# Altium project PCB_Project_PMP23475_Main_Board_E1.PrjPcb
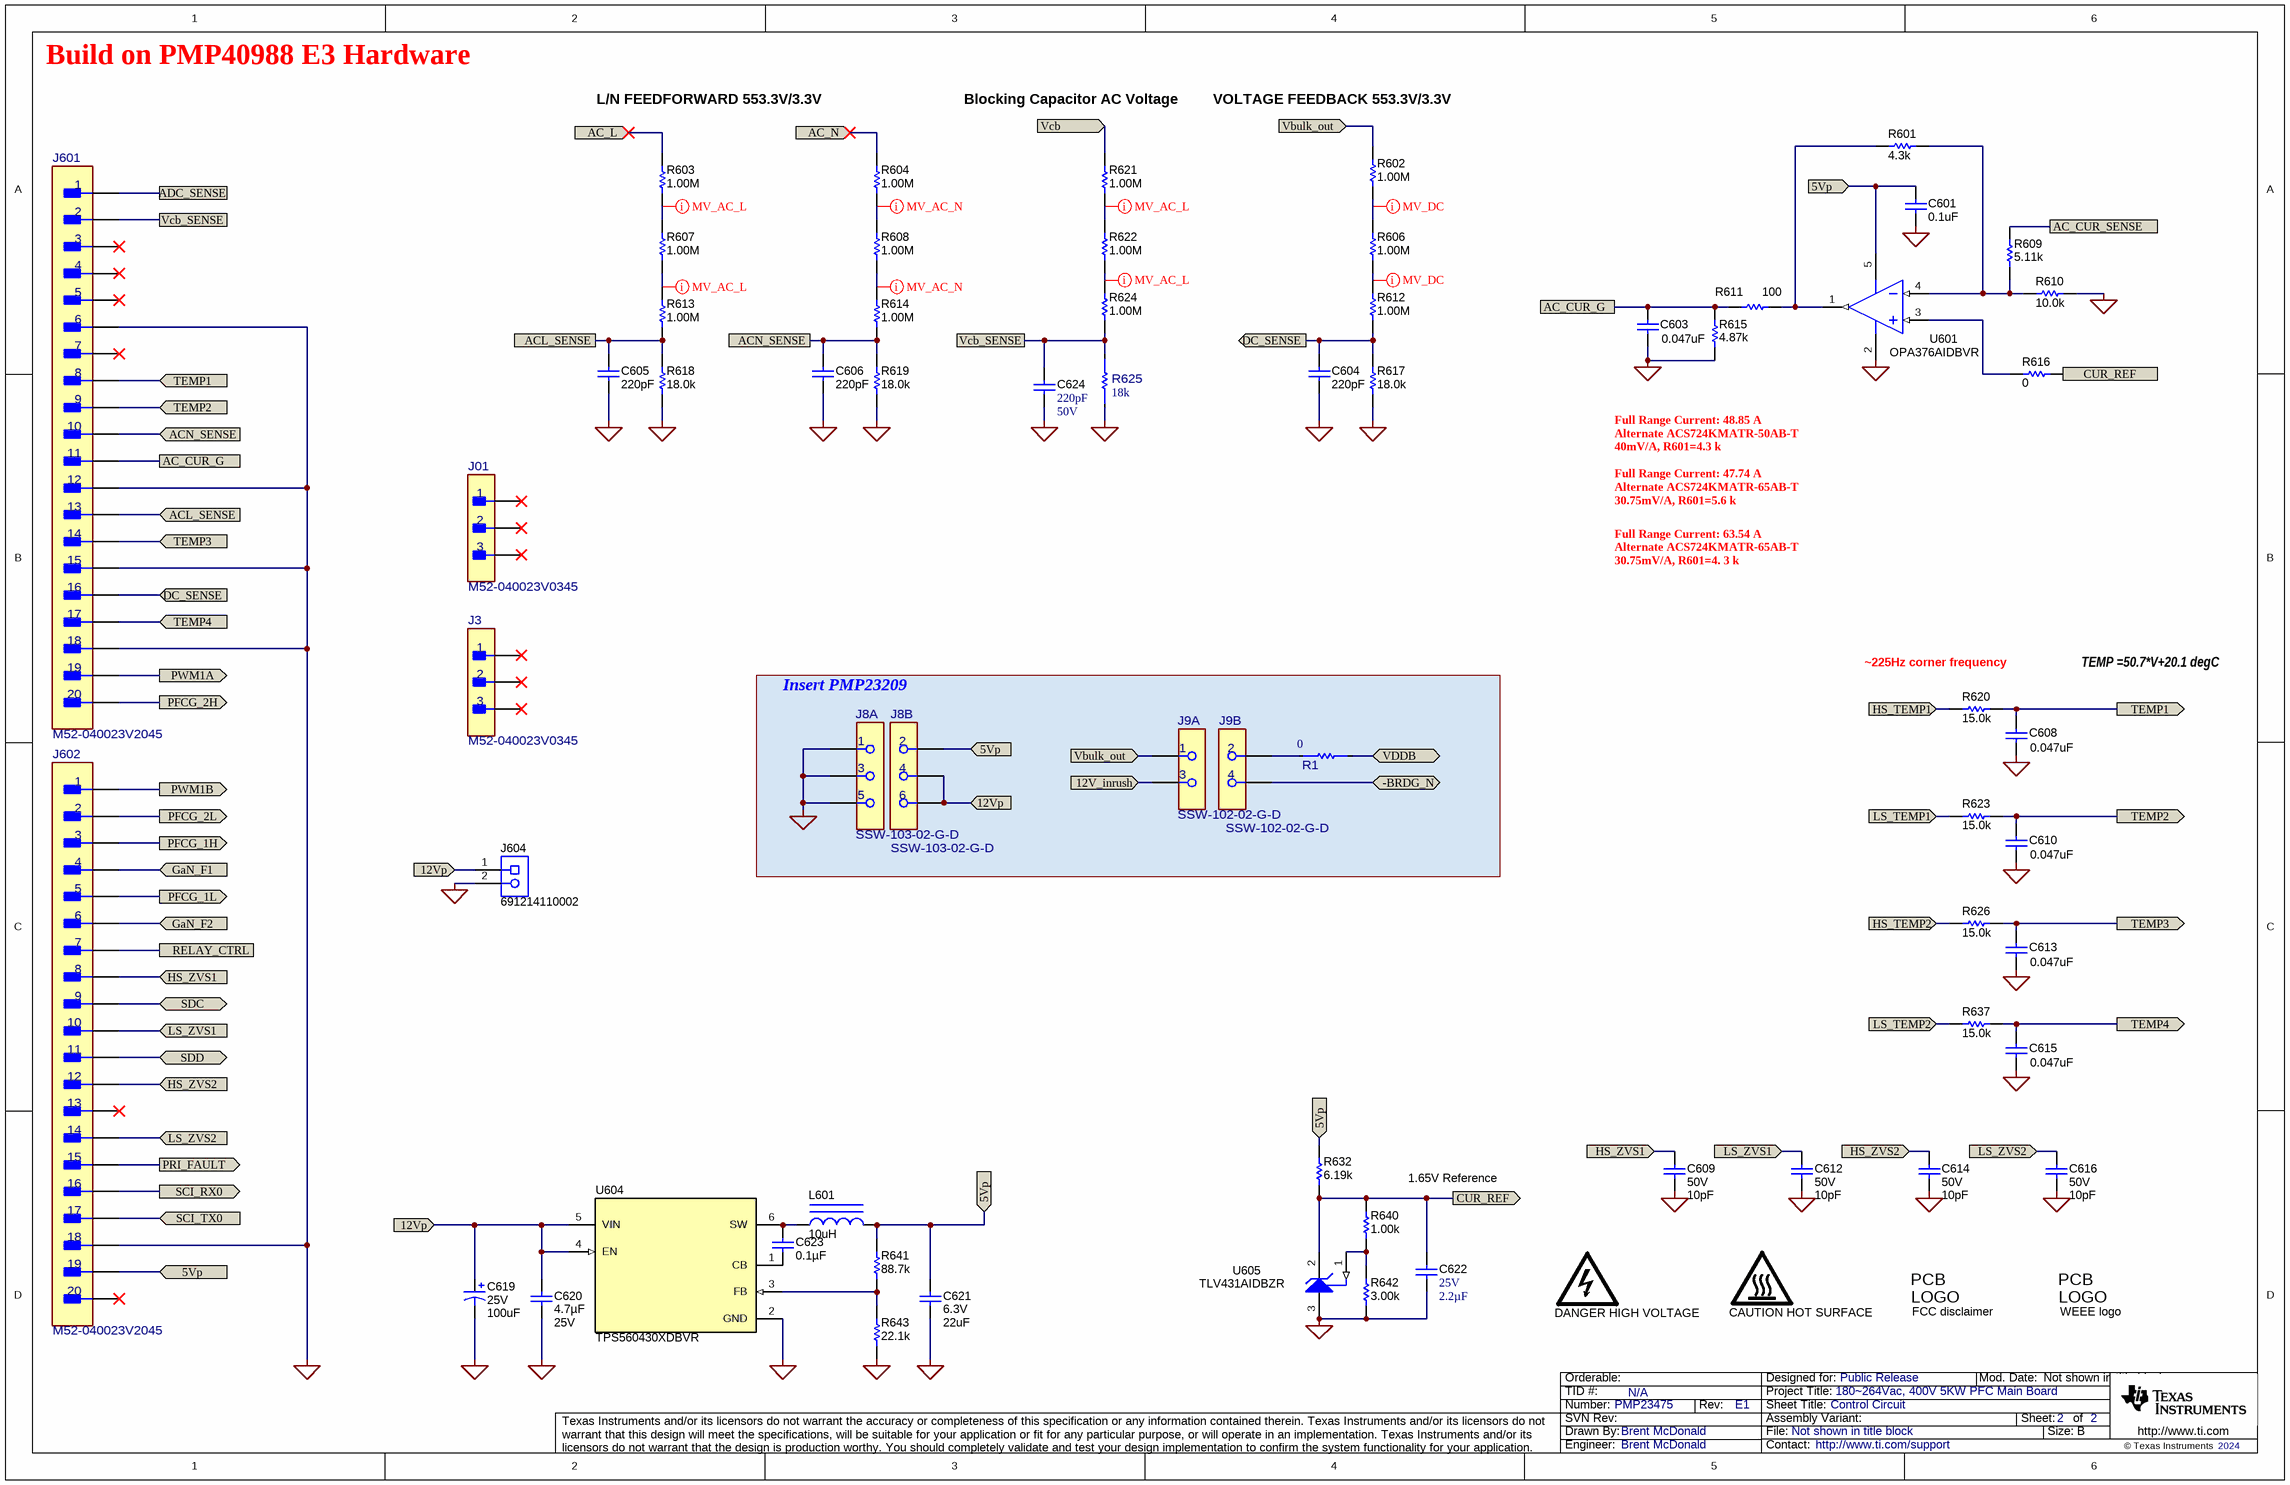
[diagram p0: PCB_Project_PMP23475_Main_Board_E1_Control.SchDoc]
CopyrightYear: 2024; PCB_Layout: Brent McDonald; PCB_Rev: E1; PRJ_Customer: Public Release; PRJ_Engineer: Brent McDonald; PRJ_Number: PMP23475; PRJ_Title: 180~264Vac, 400V 5KW PFC Main Board; SCH_Rev: E1; TechSupport: http://www.ti.com/support; TID: N/A
2 sheets, 163 parts. Net scope: flat (ports and power ports of the same name join across sheets).
Board file: PCB_Project_PPMP23475_Main_Board_E1_PCB.PcbDoc
Sheets:
  PCB_Project_PMP23475_Main_Board_E1_Control.SchDoc
  PCB_Project_PMP23475_Main_Board_E1_Power.SchDoc

## Sheet PCB_Project_PMP23475_Main_Board_E1_Control.SchDoc: Control Circuit
size 431 x 279 mm; Date: Not shown in title block; ApprovedBy: Not shown in title block; CheckedBy: Not shown in title block; Author: Not shown in title block; CompanyName: Not shown in title block; DrawnBy: Brent McDonald; Engineer: Not shown in title block; Organization: Not shown in title block; Address1: Not shown in title block; Address2: Not shown in title block; Address3: Not shown in title block; Address4: Not shown in title block; DocumentNumber: 2; Revision: Use project parameter SCH_Rev; SheetNumber: 2; SheetTotal: 2; PageSetup: Record=PageOptions¦CenterHorizontal=True¦CenterVertical=True¦PrintScale=1.00¦XCorrection=1.00¦YCorrection=1.00¦PrintKind=0¦BorderSize=5000000¦LeftOffset=0¦BottomOffset=0¦Orientation=2¦PaperLength=1000¦PaperWidth=1000¦Scale=100¦PaperSource=15¦PrintQuality=600¦MediaType=1¦DitherType=10¦PaperKind=Letter¦PrintScaleMode=1

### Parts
C601  ValueDisplayed: 0.1uF  [0402]  (hidden comment: GRM155R70J104KA01D)
C603  ValueDisplayed: 0.047uF  [0402]  (hidden comment: C1005X5R1A473K050BA)
C604  ValueDisplayed: 220pF  [0402]  (hidden comment: CC0402KRX7R9BB221)
C605  ValueDisplayed: 220pF  [0402]  (hidden comment: CC0402KRX7R9BB221)
C606  ValueDisplayed: 220pF  [0402]  (hidden comment: CC0402KRX7R9BB221)
C608  ValueDisplayed: 0.047uF  [0402]  (hidden comment: C1005X5R1A473K050BA)
C609  VDC_V: 50V  ValueDisplayed: 10pF  [0402]  (hidden comment: 885012005055)
C610  ValueDisplayed: 0.047uF  [0402]  (hidden comment: C1005X5R1A473K050BA)
C612  VDC_V: 50V  ValueDisplayed: 10pF  [0402]  (hidden comment: 885012005055)
C613  ValueDisplayed: 0.047uF  [0402]  (hidden comment: C1005X5R1A473K050BA)
C614  VDC_V: 50V  ValueDisplayed: 10pF  [0402]  (hidden comment: 885012005055)
C615  ValueDisplayed: 0.047uF  [0402]  (hidden comment: C1005X5R1A473K050BA)
C616  VDC_V: 50V  ValueDisplayed: 10pF  [0402]  (hidden comment: 885012005055)
C619  VDC_V: 25V  ValueDisplayed: 100uF  [CAPPR250W50D630H1120]  (hidden comment: EEU-EB1E101S)
C620  Cap_F: 4.7µF  VDC_V: 25V  [0805_HV]  (hidden comment: C2012X7R1E475K125AB)
C621  VDC_V: 6.3V  ValueDisplayed: 22uF  [0805_HV]  (hidden comment: CL21A226KQQNNNE)
C622  VDC_V: 25V  ValueDisplayed: 2.2µF  [0402]  (hidden comment: GRM155R61E225ME15D)
C623  ValueDisplayed: 0.1µF  [0402]  (hidden comment: CC0402KRX7R8BB104)
C624  ValueDisplayed: 220pF  VDC_V: 50V  [0402]  (hidden comment: CC0402KRX7R9BB221)
J01  M52-040023V0345  [FP-M52-040023V0345_HDR3-MFG]
J3  M52-040023V0345  [FP-M52-040023V0345_HDR3-MFG]
J8  SSW-103-02-G-D  [FP-SSW-103-02-G-D_RCPT6-MFG]  (parts A,B of 2)
J9  SSW-102-02-G-D  [FP-SSW-102-02-G-D_HDR4-MFG]  (parts A,B of 2)
J601  M52-040023V2045  [FP-M52-040023V2045_HDR20-MFG]
J602  M52-040023V2045  [FP-M52-040023V2045_HDR20-MFG]
J604  691214110002  [Wurth_691214110002]
L601  ValueDisplayed: 10uH  [WE-MAPI_3020]  (hidden comment: 74438336100)
LOGO601  CAUTION HOT SURFACE  [IEC_HotSurface_Small]  (no BOM)
LOGO602  DANGER HIGH VOLTAGE  [IEC_HighVoltage_Small]  (no BOM)
Logo603  FCC disclaimer  [FCC_disclaimer]  (no BOM)
Logo604  WEEE logo  [WEEE_Minimum]  (no BOM)
R1  value 0  [FP-ERJ-H3G0R00V_0603-MFG]  (hidden comment: ERJ-H3G0R00V)
R601  ValueDisplayed: 4.3k  [0402]  (hidden comment: RT0402FRE074K3L)
R602  ValueDisplayed: 1.00M  [1206]  (hidden comment: RC1206FR-071ML)
R603  ValueDisplayed: 1.00M  [1206]  (hidden comment: RC1206FR-071ML)
R604  ValueDisplayed: 1.00M  [1206]  (hidden comment: RC1206FR-071ML)
R606  ValueDisplayed: 1.00M  [1206]  (hidden comment: RC1206FR-071ML)
R607  ValueDisplayed: 1.00M  [1206]  (hidden comment: RC1206FR-071ML)
R608  ValueDisplayed: 1.00M  [1206]  (hidden comment: RC1206FR-071ML)
R609  ValueDisplayed: 5.11k  [0402]  (hidden comment: CRCW04025K11FKED)
R610  ValueDisplayed: 10.0k  [0402]  (hidden comment: CRCW040210K0FKED)
R611  ValueDisplayed: 100  [0402]  (hidden comment: RC0402FR-07100RL)
R612  ValueDisplayed: 1.00M  [1206]  (hidden comment: RC1206FR-071ML)
R613  ValueDisplayed: 1.00M  [1206]  (hidden comment: RC1206FR-071ML)
R614  ValueDisplayed: 1.00M  [1206]  (hidden comment: RC1206FR-071ML)
R615  ValueDisplayed: 4.87k  [0402]  (hidden comment: ERA-2AEB4871X)
R616  ValueDisplayed: 0  [0402]  (hidden comment: CRCW04020000Z0ED)
R617  ValueDisplayed: 18.0k  [0402]  (hidden comment: CRCW040218K0FKED)
R618  ValueDisplayed: 18.0k  [0402]  (hidden comment: CRCW040218K0FKED)
R619  ValueDisplayed: 18.0k  [0402]  (hidden comment: CRCW040218K0FKED)
R620  ValueDisplayed: 15.0k  [0402]  (hidden comment: RC0402FR-0715KL)
R621  ValueDisplayed: 1.00M  [1206]  (hidden comment: RC1206FR-071ML)
R622  ValueDisplayed: 1.00M  [1206]  (hidden comment: RC1206FR-071ML)
R623  ValueDisplayed: 15.0k  [0402]  (hidden comment: RC0402FR-0715KL)
R624  ValueDisplayed: 1.00M  [1206]  (hidden comment: RC1206FR-071ML)
R625  value 18k  [FP-CRCW040218K0FKEDC_0402-MFG]  (hidden comment: CRCW040218K0FKEDC)
R626  ValueDisplayed: 15.0k  [0402]  (hidden comment: RC0402FR-0715KL)
R632  ValueDisplayed: 6.19k  [0402]  (hidden comment: CRCW04026K19FKED)
R637  ValueDisplayed: 15.0k  [0402]  (hidden comment: RC0402FR-0715KL)
R640  ValueDisplayed: 1.00k  [0402]  (hidden comment: RC0402FR-071KL)
R641  ValueDisplayed: 88.7k  [0402]  (hidden comment: CRCW040288K7FKED)
R642  ValueDisplayed: 3.00k  [0402]  (hidden comment: RC0402FR-073KL)
R643  ValueDisplayed: 22.1k  [0402]  (hidden comment: CRCW040222K1FKED)
U601  OPA376AIDBVR  [DBV0005A_N]
U604  TPS560430XDBVR  [DBV0006A_N]
U605  TLV431AIDBZR  [DBZ0003A_N]

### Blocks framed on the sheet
Insert PMP23209: J8 J9 R1

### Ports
5Vp (in), 12V_inrush (in), 12Vp (in), -BRDG_N (bidir), AC_CUR_G, AC_CUR_SENSE, AC_L (in), AC_N (in), ACL_SENSE, ACL_SENSE (in), ACN_SENSE, ACN_SENSE (in), ADC_SENSE, CUR_REF (in), CUR_REF (out), DC_SENSE (in), DC_SENSE (out), GaN_F1 (in), GaN_F2 (in), HS_TEMP1 (in), HS_TEMP2 (in), HS_ZVS1 (in), HS_ZVS2 (in), LS_TEMP1 (in), LS_TEMP2 (in), LS_ZVS1 (in), LS_ZVS2 (in), PFCG_1H (out), PFCG_1L (out), PFCG_2H (out), PFCG_2L (out), PRI_FAULT (out), PWM1A (out), PWM1B (out), RELAY_CTRL, SCI_RX0 (out), SCI_TX0 (in), SDC (bidir), SDD (bidir), TEMP1 (in), TEMP1 (out), TEMP2 (in), TEMP2 (out), TEMP3 (in), TEMP3 (out), TEMP4 (in), TEMP4 (out), Vbulk_out (in), Vcb (in), Vcb_SENSE, VDDB (bidir)

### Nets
AGND: C601.1 C603.2 C604.2 C605.2 C606.2 C608.2 C609.2 C610.2 C612.2 C613.2 C614.2 C615.2 C616.2 C619.2(-) C620.2 C621.2 C622.2 C624.1 J8.1 J8.3 J8.5 J601.6 J601.12 J601.15 J601.18 J602.18 J604.2 R610.2 R615.1 R617.1 R618.1 R619.1 R625.1 R642.1 R643.1 U601.2(V-) U604.2(GND) U605.3(ANODE)
5Vp: C601.2 C621.1 J8.2 J602.19 L601.2 R632.2 R641.2 U601.5(V+) ; port 5Vp
12V_inrush: J9.3 ; port 12V_inrush
12Vp: C619.1(+) C620.1 J8.4 J8.6 J604.1 U604.4(EN) U604.5(VIN) ; port 12Vp
-BRDG_N: J9.4 ; port -BRDG_N
AC_CUR_G: C603.1 J601.11 R611.1 R615.2 ; port AC_CUR_G
AC_CUR_SENSE: R609.1 ; port AC_CUR_SENSE
AC_L: R603.2 ; port AC_L
AC_N: R604.2 ; port AC_N
ACL_SENSE: C605.1 J601.13 R613.1 R618.2 ; port ACL_SENSE
ACN_SENSE: C606.1 J601.10 R614.1 R619.2 ; port ACN_SENSE
ADC_SENSE: J601.1 ; port ADC_SENSE
CUR_REF: C622.1 R616.2 R632.1 R640.2 U605.2(CATHODE) ; port CUR_REF
DC_SENSE: C604.1 J601.16 R612.1 R617.2 ; port DC_SENSE
GaN_F1: J602.4 ; port GaN_F1
GaN_F2: J602.6 ; port GaN_F2
HS_TEMP1: R620.1 ; port HS_TEMP1
HS_TEMP2: R626.1 ; port HS_TEMP2
HS_ZVS1: C609.1 J602.8 ; port HS_ZVS1
HS_ZVS2: C614.1 J602.12 ; port HS_ZVS2
LS_TEMP1: R623.1 ; port LS_TEMP1
LS_TEMP2: R637.1 ; port LS_TEMP2
LS_ZVS1: C612.1 J602.10 ; port LS_ZVS1
LS_ZVS2: C616.1 J602.14 ; port LS_ZVS2
PFCG_1H: J602.3 ; port PFCG_1H
PFCG_1L: J602.5 ; port PFCG_1L
PFCG_2H: J601.20 ; port PFCG_2H
PFCG_2L: J602.2 ; port PFCG_2L
PRI_FAULT: J602.15 ; port PRI_FAULT
PWM1A: J601.19 ; port PWM1A
PWM1B: J602.1 ; port PWM1B
RELAY_CTRL: J602.7 ; port RELAY_CTRL
SCI_RX0: J602.16 ; port SCI_RX0
SCI_TX0: J602.17 ; port SCI_TX0
SDC: J602.9 ; port SDC
SDD: J602.11 ; port SDD
TEMP1: C608.1 J601.8 R620.2 ; port TEMP1
TEMP2: C610.1 J601.9 R623.2 ; port TEMP2
TEMP3: C613.1 J601.14 R626.2 ; port TEMP3
TEMP4: C615.1 J601.17 R637.2 ; port TEMP4
Vbulk_out: J9.1 R602.2 ; port Vbulk_out
Vcb: R621.2 ; port Vcb
Vcb_SENSE: C624.2 J601.2 R624.1 R625.2 ; port Vcb_SENSE
VDDB: R1.2 ; port VDDB
NetC623_1: C623.1 L601.1 U604.6(SW)
NetC623_2: C623.2 U604.1(CB)
NetJ9_2: J9.2 R1.1
NetR601_1: R601.1 R611.2 U601.1(OUT)
NetR601_2: R601.2 R609.2 R610.1 U601.4(IN-)
NetR602_1: R602.1 R606.2
NetR603_1: R603.1 R607.2
NetR604_1: R604.1 R608.2
NetR606_1: R606.1 R612.2
NetR607_1: R607.1 R613.2
NetR608_1: R608.1 R614.2
NetR616_1: R616.1 U601.3(IN+)
NetR621_1: R621.1 R622.2
NetR622_1: R622.1 R624.2
NetR640_1: R640.1 R642.2 U605.1(REF)
NetR641_1: R641.1 R643.2 U604.3(FB)

Not connected (* = marked no-connect by the designer): J01 1* 2* 3*; J3 1* 2* 3*; J601 3* 4* 5* 7*; J602 13* 20*

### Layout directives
net class MV_DC: NetR602_1, NetR606_1
net class MV_AC_L: NetR603_1, NetR607_1, NetR621_1, NetR622_1
net class MV_AC_N: NetR604_1, NetR608_1

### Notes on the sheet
- Build on PMP40988 E3 Hardware
- L/N FEEDFORWARD 553.3V/3.3V
- Blocking Capacitor AC Voltage
- (near R602) VOLTAGE FEEDBACK 553.3V/3.3V
- Full Range Current: 48.85 A
  Alternate ACS724KMATR-50AB-T 40mV/A, R601=4.3 k
- Full Range Current: 47.74 A
  Alternate ACS724KMATR-65AB-T
  30.75mV/A, R601=5.6 k
- Full Range Current: 63.54 A
  Alternate ACS724KMATR-65AB-T
  30.75mV/A, R601=4. 3 k
- |25Hz corner frequency
- TEMP =50.7*V+20.1 degC
- (near R640) 1.65V Reference

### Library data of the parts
C601 = GRM155R70J104KA01D: CAP, CERM, 0.1uF, 6.3V, +/-10%, X7R, 0402; Manufacturer: MuRata; Polarized: N; CompType: Capacitor; U/M: EA; Cap_F: 0.0000001; Tolerance_%: 10; Value1: Unknown; VDC_V: 6.3; TaMin_C: -55; TaMax_C: 125
C603 C608 C610 C613 C615 = CMP-0006266-2: CAP, CERM, 0.047 uF, 10 V, +/- 10%, X5R, 0402; Manufacturer: TDK; TaMin_C: -55°C; Polarized: N; SizeAreaWB_mm2: 3; Value1: Unknown; U/M: EA; TaMax_C: 85°C; SizeZ_mm: 0.6; SizeX_mm: 1; SizeY_mm: 0.5; Value2: 10V; CompType: Capacitor; Cap_F: 47nF; AEC Category: Q200
C604-C606 = CMP-0860558-1: CAP, CERM, 220 pF, 50 V,+/- 10%, X7R, 0402; Manufacturer: Yageo; SizeAreaWB_mm2: 3; CompType: Capacitor; SizeZ_mm: 0.6; Value: 220pF; TaMax_C: 125°C; U/M: EA; AEC Category: Q200; SizeX_mm: 1; AEC Qualified: N; TaMin_C: -55°C; Value2: 50V; SizeArea_mm2: 0.5
C609 C612 C614 C616 = CMP-0006215-2: CAP, CERM, 10 pF, 50 V, +/- 5%, C0G/NP0, 0402; Manufacturer: Wurth Elektronik; TaMin_C: -55°C; Polarized: N; SizeAreaWB_mm2: 3; Value1: Unknown; U/M: EA; Value: 10pF; TaMax_C: 125°C; SizeZ_mm: 0.6; SizeX_mm: 1; SizeY_mm: 0.5; CompType: Capacitor; AEC Category: Q200
C619 = CMP-0010333-1: CAP, AL, 100 uF, 25 V, +/- 20%, TH; Manufacturer: Panasonic; TaMin_C: -40°C; Polarized: Y; SizeAreaWB_mm2: 68.89; Value1: Unknown; U/M: EA; Value: 100uF; TaMax_C: 105°C; SizeZ_mm: 11.2; SizeX_mm: 6.3; Cap_Case: Radial 6.3x11.2; SizeArea_mm2: 39.69; CompType: Capacitor; AEC Qualified: N; Cap_F: 100µF; IRMS_A: 95mA; AEC Category: Q200
C620 = CMP-0007870-2: CAP, CERM, 4.7 uF, 25 V, +/- 10%, X7R, 0805; Manufacturer: TDK; TaMin_C: -55°C; Polarized: N; SizeAreaWB_mm2: 6.75; Value1: Unknown; U/M: EA; Value: 4.7uF; TaMax_C: 125°C; SizeZ_mm: 1.45; SizeX_mm: 2; SizeY_mm: 1.25; Cap_Case: 0805; SizeArea_mm2: 2.5; AEC Category: Q200
C621 = CMP-0007989-2: CAP, CERM, 22 uF, 6.3 V, +/- 10%, X5R, 0805; Manufacturer: Samsung Electro-Mechanics; TaMin_C: -55°C; Polarized: N; SizeAreaWB_mm2: 6.75; Value1: Unknown; U/M: EA; Value: 22uF; TaMax_C: 85°C; SizeZ_mm: 1.45; SizeX_mm: 2; SizeY_mm: 1.25; Cap_Case: 0805; SizeArea_mm2: 2.5; Cap_F: 22µF; AEC Category: Q200
C622 = CMP-0081010-1: CAP, CERM, 2.2 µF, 25 V,+/- 20%, X5R, 0402; Manufacturer: MuRata; SizeAreaWB_mm2: 3; SizeArea_mm2: 0.5; AEC Qualified: N; AEC Category: Q200; Value: 2.2uF; TaMax_C: 85°C; SizeZ_mm: 0.6; TaMin_C: -55°C; U/M: EA; SizeX_mm: 1
C623 = CMP-0860555-1: CAP, CERM, 0.1 µF, 25 V,+/- 10%, X7R, 0402; Manufacturer: Yageo; SizeArea_mm2: 0.5; AEC Qualified: N; CompType: Capacitor; SizeX_mm: 1; U/M: EA; Value: 0.1uF; TaMin_C: -55°C; VDC_V: 25V; SizeZ_mm: 0.6; Cap_F: 100nF; TaMax_C: 125°C; SizeAreaWB_mm2: 3; AEC Category: Q200
C624 = CMP-0860558-1: CAP, CERM, 220 pF, 50 V,+/- 10%, X7R, 0402; Manufacturer: Yageo; SizeAreaWB_mm2: 3; SizeZ_mm: 0.6; Value: 220pF; TaMax_C: 125°C; U/M: EA; AEC Category: Q200; SizeX_mm: 1; AEC Qualified: N; TaMin_C: -55°C; SizeArea_mm2: 0.5
J01 J3 = CMP-0097093-1: Connector Header Through Hole 3 position 0.050" (1.27mm); Manufacturer: Harwin; SizeZ_mm: 6.84mm; Conn Gender: Male; Row_Count: 1; AEC Qualified: No; ContactFinish: Gold,Nickel; Is Female: yes; Current_A: 1A; Conn Orientation: Vertical
J8 = CMP-0090625-1: 6 Position Receptacle Connector  Through Hole; Manufacturer: SAMTEC; Conn Gender: Female; Current_A: 4.7A; Conn Orientation: Vertical; Is Female: yes; Row_Count: 2; SizeZ_mm: 8.64mm; Voltage_V: 655V; AEC Qualified: No; ContactFinish: Gold,Nickel; DUT-Pitch_mm: 2.54mm
J9 = CMP-0090624-1: Board-To-Board Connector, Dual, SSW Series, 4 Contacts, Receptacle, 2.54 mm, Through Hole, 2 Rows; Manufacturer: Samtec; DUT-Pitch_mm: 2.54mm; SizeZ_mm: 8.64mm; Current_A: 4.7A; ContactFinish: Gold,Nickel; Conn Gender: Female; Voltage_V: 655V; Is Female: yes; AEC Qualified: No; Row_Count: 2; Conn Orientation: Vertical
J601 J602 = CMP-0097094-1: Connector Header Through Hole 20 position 0.050" (1.27mm); Manufacturer: Harwin; AEC Qualified: No; Current_A: 1A; Conn Gender: Male; Conn Orientation: Vertical; ContactFinish: Gold,Nickel; SizeZ_mm: 6.84mm; Row_Count: 1
J604 = CMP-0054825-2: Terminal Block, 3.5mm, 2x1, Tin, TH; Manufacturer: Wurth Elektronik; Pitch_mm: 3.5; CT: TRUE; CNHeader: FALSE; Voltage_V: 300V; Gender: Female; Cert_UL: Y; Row_Count: 1; Current_A: 10A
L601 = CMP-0064157-1: Inductor, Shielded, 10 uH, 1.2 A, 0.322 ohm, SMD; Manufacturer: Wurth Elektronik; Isat: 2.35A @ 20% inductance drop; Irms: 1.2A @ 40C rise; Green_Lifecycle: Active; SizeAreaWB_mm2: 16; DCR_ohm: 3.22d; Green_REACh: Passed; Value: 10uH; Imax_A: 1.2A; SizeZ_mm: 2; SizeX_mm: 3; SizeArea_mm2: 9; Ind_H: 10µH; AEC Qualified: N; AEC Category: Q200
LOGO601 = CMP-0074837-1: IEC 61010-1 Hot Surface Warning; Library Reference: IEC_HotSurface; SymbolCreator: a0412235
LOGO602 = CMP-0074835-1: IEC 61010-1 High Voltage Warning; Library Reference: IEC_HighVoltage; SymbolCreator: a0412235
Logo603 = CMP-0074847-1: FCC_disclaimer; Library Reference: Logo
Logo604 = CMP-0074769-1
R1 = CMP-0097467-1: 0 Ohms Jumper 0.125W, 1/8W Chip Resistor 0603 (1608 Metric) Automotive AEC-Q200 Thick Film; Manufacturer: Panasonic; VDC_V: 75V; Power_W: 125mW; AEC Qualified: Yes; SizeZ_mm: 0.55mm; AEC Grade: Grade 0
R601 = CMP-0026408-2: RES, 4.3 k, 1%, 0.063 W, 0402; Manufacturer: Yageo; Power_W: 63mW; TempCo: 50ppm/C; Value_Code: 4k3; Value: 4.3k; EIA_Code: E96; SizeX_mm: 1; SizeY_mm: 0.5; SizeZ_mm: 0.6; Value2: 0.063W; CompType: Resistor; AEC Qualified: Y; VDC_V: 50V; AEC Category: Q200; AEC Grade: 0
R602-R604 R606-R608 R612-R614 R621 R622 R624 = CMP-0018027-2: RES, 1.00 M, 1%, 0.25 W, 1206; Manufacturer: Yageo America; Power_W: 250mW; TempCo: 100 ppm/C; Value_Code: 1M00; U/M: EA; Value: 1.00Meg; EIA_Code: E96; Res_ohm: 1M; SizeX_mm: 3.2; SizeY_mm: 1.6; SizeZ_mm: 1.35; Value2: 0.25W; SizeArea_mm2: 5.12; VDC_V: 200V; AEC Category: Q200
R609 = CMP-0026463-2: RES, 5.11 k, 1%, 0.063 W, AEC-Q200 Grade 0, 0402; Manufacturer: Vishay-Dale; Power_W: 63mW; TempCo: 100 ppm/C; Value_Code: 5k11; Value: 5.11k; EIA_Code: E96; SizeX_mm: 1; SizeY_mm: 0.5; SizeZ_mm: 0.6; Value2: 0.063W; AEC Qualified: Y; VDC_V: 50V; AEC Category: Q200; AEC Grade: 0
R610 = CMP-0025958-3: RES, 10.0 k, 1%, 0.063 W, AEC-Q200 Grade 0, 0402; Manufacturer: Vishay-Dale; Power_W: 63mW; TempCo: 100 ppm/C; Value_Code: 10k0; Value: 10.0k; EIA_Code: E96; Res_ohm: 10k; SizeX_mm: 1; SizeY_mm: 0.5; SizeZ_mm: 0.6; Value2: 0.063W; AEC Qualified: Y; VDC_V: 50V; AEC Category: Q200; AEC Grade: 0
R611 = CMP-0026722-1: RES, 100, 1%, 0.063 W, 0402; Manufacturer: Yageo America; Power_W: 63mW; TempCo: 100 ppm/C; Value_Code: 100R; U/M: EA; Value: 100; EIA_Code: E96; SizeX_mm: 1; SizeY_mm: 0.5; SizeZ_mm: 0.6; Value2: 0.063W; AEC Qualified: N; VDC_V: 50V; AEC Category: Q200
R615 = CMP-0026781-1: RES, 4.87 k, 0.1%, 0.062 W, AEC-Q200 Grade 0, 0402; Manufacturer: Panasonic; Power_W: 62mW; TempCo: 25 ppm/C; Value_Code: 4k87; U/M: EA; Value: 4.87k; EIA_Code: E192; SizeX_mm: 1; SizeY_mm: 0.5; SizeZ_mm: 0.6; Value2: 0.062W; AEC Qualified: Y; VDC_V: 25V; AEC Grade: 0; AEC Category: Q200
R616 = CMP-0026822-3: RES, 0, 5%, 0.063 W, AEC-Q200 Grade 0, 0402; Manufacturer: Vishay-Dale; Power_W: 63mW; TempCo: 200 ppm/C; Value_Code: 0000; Value: 0; EIA_Code: E24; SizeX_mm: 1; SizeY_mm: 0.5; SizeZ_mm: 0.6; Value2: 0.063W; AEC Qualified: Y; VDC_V: 50V; AEC Category: Q200
R617-R619 = CMP-0026058-3: RES, 18.0 k, 1%, 0.063 W, AEC-Q200 Grade 0, 0402; Manufacturer: Vishay-Dale; Power_W: 63mW; TempCo: 100 ppm/C; Value_Code: 18k0; Value: 18.0k; Res_ohm: 18k; SizeX_mm: 1; SizeY_mm: 0.5; SizeZ_mm: 0.6; Value2: 0.063W; AEC Qualified: Y; VDC_V: 50V; AEC Grade: 0; AEC Category: Q200
R620 R623 R626 R637 = CMP-0078583-1: RES, 15.0 k, 1%, 0.063 W, 0402; Manufacturer: Yageo America; Power_W: 63mW; Green_Lifecycle: Active; TempCo: 100 ppm/C; Value_Code: 15k0; Green_REACh: Passed; Value: 15.0k; EIA_Code: E96; Res_ohm: 15k; SizeX_mm: 1; SizeY_mm: 0.5; SizeZ_mm: 0.6; Value2: 0.063W; AEC Qualified: N; AEC Category: Q200
R625 = CMP-0094741-1: Res Thick Film 0402 18K Ohm 1% 1/16W ±100ppm/°C Molded SMD Paper T/R; Manufacturer: Vishay; VDC_V: 50V; SizeZ_mm: 0.35mm; AEC Qualified: No; Power_W: 63mW
R632 = CMP-0026513-2: RES, 6.19 k, 1%, 0.063 W, AEC-Q200 Grade 0, 0402; Manufacturer: Vishay-Dale; Power_W: 63mW; TempCo: 100 ppm/C; Value_Code: 6k19; Value: 6.19k; EIA_Code: E96; SizeX_mm: 1; SizeY_mm: 0.5; SizeZ_mm: 0.6; Value2: 0.063W; AEC Qualified: Y; VDC_V: 50V; AEC Category: Q200; AEC Grade: 0
R640 = CMP-0026725-1: RES, 1.00 k, 1%, 0.0625 W, 0402; Manufacturer: Yageo America; Power_W: 62.5mW; TempCo: 100 ppm/C; Value_Code: 1k00; U/M: EA; Value: 1.00k; EIA_Code: E96; Res_ohm: 1k; SizeX_mm: 1; SizeY_mm: 0.5; SizeZ_mm: 0.6; AEC Qualified: N; VDC_V: 50V; AEC Category: Q200
R641 = CMP-0026586-2: RES, 88.7 k, 1%, 0.063 W, AEC-Q200 Grade 0, 0402; Manufacturer: Vishay-Dale; Power_W: 63mW; TempCo: 100 ppm/C; Value_Code: 88k7; Value: 88.7k; EIA_Code: E96; SizeX_mm: 1; SizeY_mm: 0.5; SizeZ_mm: 0.6; Value2: 0.063W; AEC Qualified: Y; VDC_V: 50V; AEC Category: Q200; AEC Grade: 0
R642 = CMP-0026733-1: RES, 3.00 k, 1%, 0.0625 W, 0402; Manufacturer: Yageo America; Power_W: 62.5mW; TempCo: 100 ppm/C; Value_Code: 3k00; U/M: EA; Value: 3.00k; Res_ohm: 3k; SizeX_mm: 1; SizeY_mm: 0.5; SizeZ_mm: 0.6; AEC Qualified: N; VDC_V: 50V; AEC Category: Q200
R643 = CMP-0026178-2: RES, 22.1 k, 1%, 0.063 W, AEC-Q200 Grade 0, 0402; Manufacturer: Vishay-Dale; Power_W: 63mW; TempCo: 100 ppm/C; Value_Code: 22k1; Value: 22.1k; EIA_Code: E96; SizeX_mm: 1; SizeY_mm: 0.5; SizeZ_mm: 0.6; Value2: 0.063W; AEC Qualified: Y; VDC_V: 50V; AEC Category: Q200; AEC Grade: 0
U601 = CMP-0041017-1: Precision, Low Noise, Low Iq Operational Amplifier, 2.2 to 5.5 V, -40 to 125 degC, 5-pin SOT23 (DBV5), Green (RoHS & no Sb/Br); Manufacturer: Texas Instruments; IIB(Max)(pA): 10; Number of Channels: 1; Sub Family: Low Input Bias Current Amp (<=10pA), Low Noise Amp (<=10nV/rtHz), Low Offset Voltage Amplifier (<=500uV), Low Supply Voltage Amplifier (<=2.7V), Precision Amplifier; Vio (25C)(Max)(mV): 0.025; Offset Drift(Typ)(uV/C): 0.32; Total Supply Voltage(Max)(+5V is 5, +/-5V is 10): 5.5; Total Supply Voltage(Min)(+5V is 5, +/-5V is 10): 2.2; Slew Rate(Typ)(V/us): 2; Iq per channel(Max)(mA): 0.95; CMRR(Min)(dB): 76; Vn at 1kHz(Typ)(nV/rtHz): 7.5
U604 = CMP-0065097-3: 4V to 36 V 0.6 A Synchronous Step-Down Converter, DBV0006A (SOT-23-6); Manufacturer: Texas Instruments; Alternate PartNumber: TPS560430XDBVT; SizeX_mm: 2.8; SizeY_mm: 2.9; CompType: IC; SizeZ_mm: 1.45; SizeArea_mm2: 8.12; SizeAreaWB_mm2: 14.82; U/M: EA
U605 = CMP-0033044-1: Low Voltage Adjustable Precision Shunt Regulator, 39 ppm / degC, 15 mA, -40 to 85 degC, 3-pin SOT-23 (DBZ), Green (RoHS & no Sb/Br); Manufacturer: Texas Instruments; VO Adj(Max)(V): 6; Temp Coeff(Max)(ppm/ degree C): 129; Min Iz for Regulation(uA): 80; Iout/Iz(Max)(mA): 15; Rating: Catalog; VO Adj(Min)(V): 1.24; Initial Accuracy @ 25/deg C(%): 1; SubFamily: Shunt Voltage Reference; Temp Coeff(Typ)(ppm/ degree C): 39

## Sheet PCB_Project_PMP23475_Main_Board_E1_Power.SchDoc: Power Stage
size 431 x 279 mm; Date: Not shown in title block; ApprovedBy: Not shown in title block; CheckedBy: Not shown in title block; Author: Not shown in title block; CompanyName: Not shown in title block; DrawnBy: Brent McDonald; Engineer: Not shown in title block; Organization: Not shown in title block; Address1: Not shown in title block; Address2: Not shown in title block; Address3: Not shown in title block; Address4: Not shown in title block; DocumentNumber: 1; Revision: Use project parameter SCH_Rev; SheetNumber: 1; SheetTotal: 2; PageSetup: Record=PageOptions¦CenterHorizontal=True¦CenterVertical=True¦PrintScale=1.00¦XCorrection=1.00¦YCorrection=1.00¦PrintKind=0¦BorderSize=5000000¦LeftOffset=0¦BottomOffset=0¦Orientation=2¦PaperLength=1000¦PaperWidth=1000¦Scale=100¦PaperSource=15¦PrintQuality=600¦MediaType=1¦DitherType=10¦PaperKind=Letter¦PrintScaleMode=1
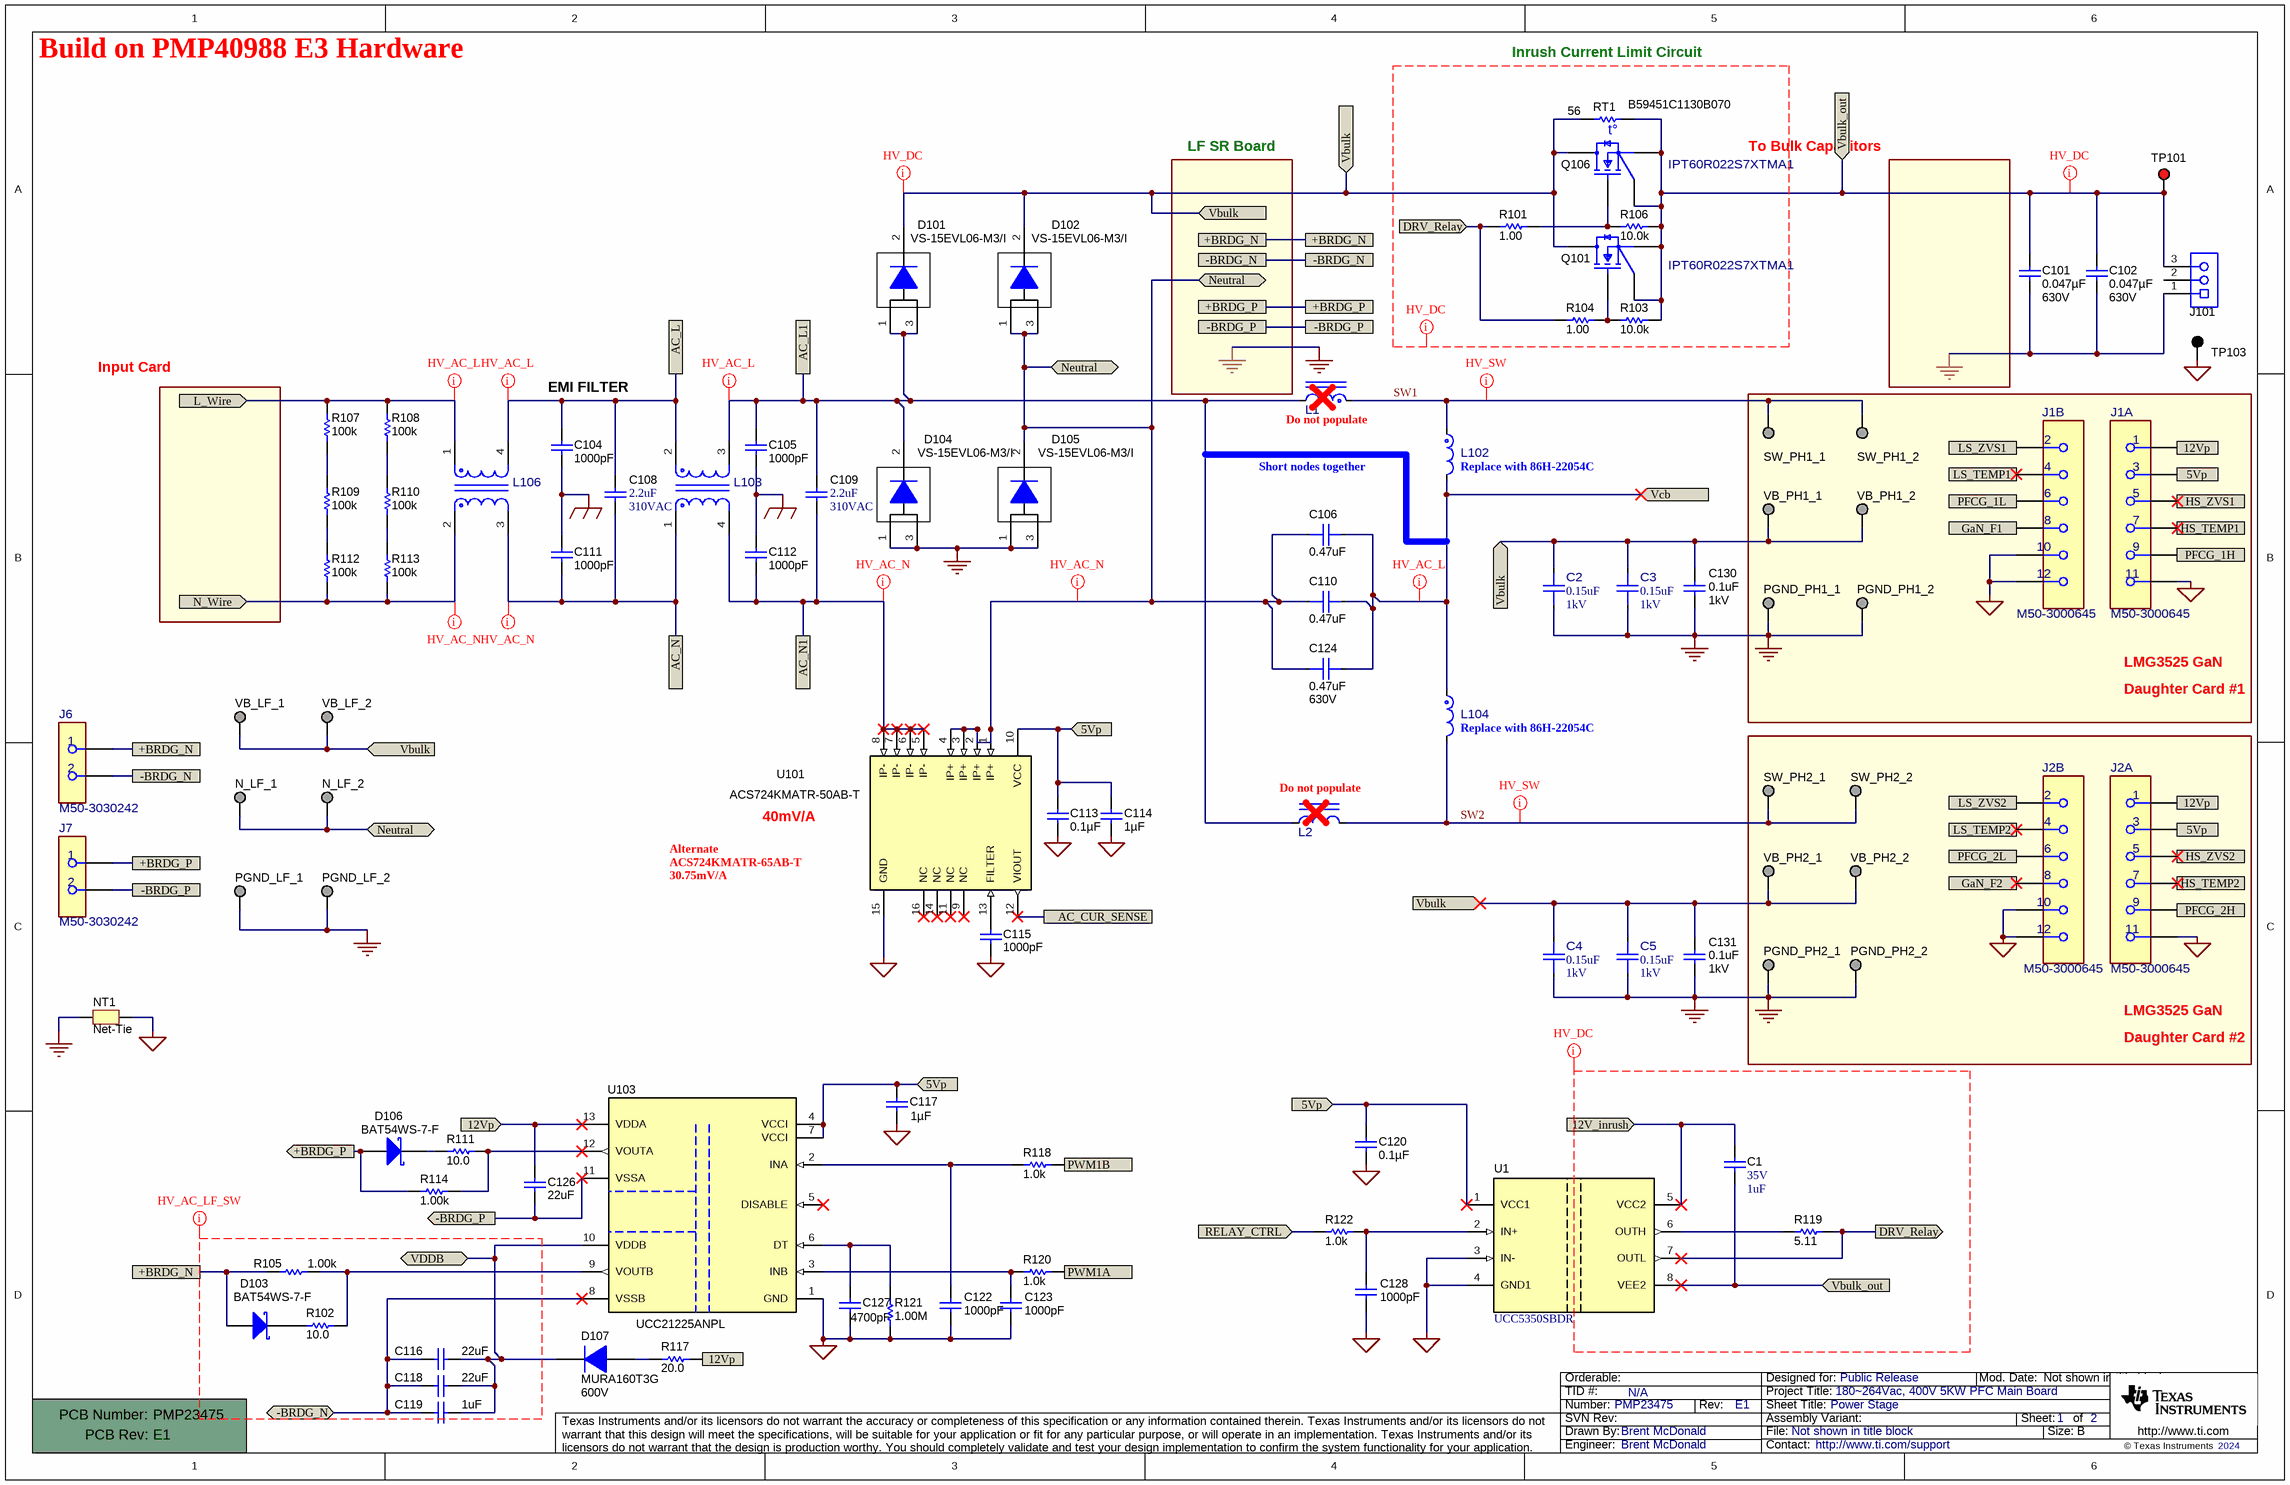
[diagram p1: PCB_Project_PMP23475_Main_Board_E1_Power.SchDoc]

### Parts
!PCB101  Printed Circuit Board  (value not drawn)  (mechanical)
C1  VDC_V: 35V  ValueDisplayed: 1uF  [0603]  (hidden comment: GMK107BJ105KA-T)
C2  ValueDisplayed: 0.15uF  VDC_V: 1kV  [FP-C2225C154KDRAC7800_2225-MFG]  (hidden comment: C2225C154KDRAC7800)
C3  ValueDisplayed: 0.15uF  VDC_V: 1kV  [FP-C2225C154KDRAC7800_2225-MFG]  (hidden comment: C2225C154KDRAC7800)
C4  ValueDisplayed: 0.15uF  VDC_V: 1kV  [FP-C2225C154KDRAC7800_2225-MFG]  (hidden comment: C2225C154KDRAC7800)
C5  ValueDisplayed: 0.15uF  VDC_V: 1kV  [FP-C2225C154KDRAC7800_2225-MFG]  (hidden comment: C2225C154KDRAC7800)
C101  ValueDisplayed: 0.047µF  Value2: 630V  [1210_220]  (hidden comment: GRM32DR72J473KW01L)
C102  ValueDisplayed: 0.047µF  Value2: 630V  [1210_220]  (hidden comment: GRM32DR72J473KW01L)
C104  ValueDisplayed: 1000pF  [Y_CAP]  (hidden comment: DE2E3SA102MN3AY02F)
C105  ValueDisplayed: 1000pF  [Y_CAP]  (hidden comment: DE2E3SA102MN3AY02F)
C106  ValueDisplayed: 0.47uF  [FP-R523I347050P3K_RADIAL-MFG]  (hidden comment: R523I347050P3K)
C108  2.2uF  Rated Voltage: 310VAC  [WCAP-FTXX_L26W15H25]
C109  2.2uF  Rated Voltage: 310VAC  [WCAP-FTXX_L26W15H25]
C110  ValueDisplayed: 0.47uF  [FP-R523I347050P3K_RADIAL-MFG]  (hidden comment: R523I347050P3K)
C111  ValueDisplayed: 1000pF  [Y_CAP]  (hidden comment: DE2E3SA102MN3AY02F)
C112  ValueDisplayed: 1000pF  [Y_CAP]  (hidden comment: DE2E3SA102MN3AY02F)
C113  ValueDisplayed: 0.1µF  [0402]  (hidden comment: CC0402KRX7R8BB104)
C114  ValueDisplayed: 1µF  [0603]  (hidden comment: GRM185R60J105KE26D)
C115  ValueDisplayed: 1000pF  [0402]  (hidden comment: GRM155R60J102KA01D)
C116  ValueDisplayed: 22uF  [0805_HV]  (hidden comment: C2012X5R1C226M125AC)
C117  ValueDisplayed: 1µF  [0402]  (hidden comment: CC0402MRX5R6BB105)
C118  ValueDisplayed: 22uF  [0805_HV]  (hidden comment: C2012X5R1C226M125AC)
C119  ValueDisplayed: 1uF  [0603]  (hidden comment: C1608X7R1E105K080AB)
C120  ValueDisplayed: 0.1µF  [0402]  (hidden comment: CC0402KRX7R8BB104)
C122  ValueDisplayed: 1000pF  [0402]  (hidden comment: C0402C102K5RACTU)
C123  ValueDisplayed: 1000pF  [0402]  (hidden comment: C0402C102K5RACTU)
C124  ValueDisplayed: 0.47uF  VDC_V: 630V  [FP-R523I347050P3K_RADIAL-MFG]  (hidden comment: R523I347050P3K)
C126  ValueDisplayed: 22uF  [0805_HV]  (hidden comment: C2012X5R1C226M125AC)
C127  ValueDisplayed: 4700pF  [0402]  (hidden comment: CC0402KRX7R8BB472)
C128  ValueDisplayed: 1000pF  [0402]  (hidden comment: C0402C102K5RACTU)
C130  ValueDisplayed: 0.1uF  VDC_V: 1kV  [1812_254]  (hidden comment: C1812W104KDRACTU)
C131  ValueDisplayed: 0.1uF  VDC_V: 1kV  [1812_254]  (hidden comment: C1812W104KDRACTU)
D101  VS-15EVL06-M3/I  [DPAK]
D102  VS-15EVL06-M3/I  [DPAK]
D103  BAT54WS-7-F  [SOD-323]
D104  VS-15EVL06-M3/I  [DPAK]
D105  VS-15EVL06-M3/I  [DPAK]
D106  BAT54WS-7-F  [SOD-323]
D107  MURA160T3G  value 600V  [SMA]
J1  M50-3000645  [FP-M50-3000645_HDR12-MFG]  (parts A,B of 2)
J2  M50-3000645  [FP-M50-3000645_HDR12-MFG]  (parts A,B of 2)
J6  M50-3030242  [FP-M50-3030242_HDR2-MFG]
J7  M50-3030242  [FP-M50-3030242_HDR2-MFG]
J101  282856-3  [TE_282856-3]  (value not drawn)
L1  PAL6493.144NL  [FP-PAL6493.144NL_PTH_IND_36MM0_33MM0-MFG]  (value not drawn)
L2  PAL6493.144NL  [FP-PAL6493.144NL_PTH_IND_36MM0_33MM0-MFG]  (value not drawn)
L102  86H-22021C  [FP-86H-22021C_PTH_IND_30MM0_14MM2-MFG]  (value not drawn)
L103  ARCDC302030E282N2B  [FP-ARCDC302030E282N2B_PTH_30MM0_20MM0-MFG]  (value not drawn)
L104  86H-22021C  [FP-86H-22021C_PTH_IND_30MM0_14MM2-MFG]  (value not drawn)
L106  YXS80660T  [FP-YXS80660T_PTH_30MM0_19MM0-MFG]  (value not drawn)
N_LF_1  0312-0-15-15-34-27-10-0  [Mill-Max_0312-0-15-15-34-27-10-0]  (value not drawn)
N_LF_2  0312-0-15-15-34-27-10-0  [Mill-Max_0312-0-15-15-34-27-10-0]  (value not drawn)
NT1  Net-Tie  [Net-Tie_50milWide_30milLong]  (net tie, no BOM)
PGND_LF_1  0312-0-15-15-34-27-10-0  [Mill-Max_0312-0-15-15-34-27-10-0]  (value not drawn)
PGND_LF_2  0312-0-15-15-34-27-10-0  [Mill-Max_0312-0-15-15-34-27-10-0]  (value not drawn)
PGND_PH1_1  0312-0-15-15-34-27-10-0  [Mill-Max_0312-0-15-15-34-27-10-0]  (value not drawn)
PGND_PH1_2  0312-0-15-15-34-27-10-0  [Mill-Max_0312-0-15-15-34-27-10-0]  (value not drawn)
PGND_PH2_1  0312-0-15-15-34-27-10-0  [Mill-Max_0312-0-15-15-34-27-10-0]  (value not drawn)
PGND_PH2_2  0312-0-15-15-34-27-10-0  [Mill-Max_0312-0-15-15-34-27-10-0]  (value not drawn)
Q101  IPT60R022S7XTMA1  [FP-IPT60R080G7XTMA1_HSOF-8-MFG]
Q106  IPT60R022S7XTMA1  [FP-IPT60R080G7XTMA1_HSOF-8-MFG]
R101  ValueDisplayed: 1.00  [0603]  (hidden comment: RC0603FR-071RL)
R102  ValueDisplayed: 10.0  [0603]  (hidden comment: RC0603FR-0710RL)
R103  ValueDisplayed: 10.0k  [0603]  (hidden comment: RC0603FR-0710KL)
R104  ValueDisplayed: 1.00  [0603]  (hidden comment: RC0603FR-071RL)
R105  ValueDisplayed: 1.00k  [0603]  (hidden comment: RC0603FR-071KL)
R106  ValueDisplayed: 10.0k  [0603]  (hidden comment: RC0603FR-0710KL)
R107  ValueDisplayed: 100k  [1206]  (hidden comment: RC1206FR-07100KL)
R108  ValueDisplayed: 100k  [1206]  (hidden comment: RC1206FR-07100KL)
R109  ValueDisplayed: 100k  [1206]  (hidden comment: RC1206FR-07100KL)
R110  ValueDisplayed: 100k  [1206]  (hidden comment: RC1206FR-07100KL)
R111  ValueDisplayed: 10.0  [0603]  (hidden comment: RC0603FR-0710RL)
R112  ValueDisplayed: 100k  [1206]  (hidden comment: RC1206FR-07100KL)
R113  ValueDisplayed: 100k  [1206]  (hidden comment: RC1206FR-07100KL)
R114  ValueDisplayed: 1.00k  [0603]  (hidden comment: RC0603FR-071KL)
R117  ValueDisplayed: 20.0  [0603]  (hidden comment: RC0603FR-0720RL)
R118  value 1.0k  [0402]  (hidden comment: CRCW04021K00JNED)
R119  ValueDisplayed: 5.11  [0603]  (hidden comment: RC0603FR-075R11L)
R120  value 1.0k  [0402]  (hidden comment: CRCW04021K00JNED)
R121  ValueDisplayed: 1.00M  [0402]  (hidden comment: RC0402FR-071ML)
R122  value 1.0k  [0402]  (hidden comment: CRCW04021K00JNED)
RT1  B59451C1130B070  value 56  [S237]
SW_PH1_1  0312-0-15-15-34-27-10-0  [Mill-Max_0312-0-15-15-34-27-10-0]  (value not drawn)
SW_PH1_2  0312-0-15-15-34-27-10-0  [Mill-Max_0312-0-15-15-34-27-10-0]  (value not drawn)
SW_PH2_1  0312-0-15-15-34-27-10-0  [Mill-Max_0312-0-15-15-34-27-10-0]  (value not drawn)
SW_PH2_2  0312-0-15-15-34-27-10-0  [Mill-Max_0312-0-15-15-34-27-10-0]  (value not drawn)
TP101  Vo  [Keystone5000]  (value not drawn)
TP103  PGND_PFC  [Keystone5001]  (value not drawn)
U1  UCC5350SBDR  [D0008B_HV]
U101  ACS724KMATR-50AB-T  [SOIC-16]
U103  UCC21225ANPL  [NPL0013A]
VB_LF_1  0312-0-15-15-34-27-10-0  [Mill-Max_0312-0-15-15-34-27-10-0]  (value not drawn)
VB_LF_2  0312-0-15-15-34-27-10-0  [Mill-Max_0312-0-15-15-34-27-10-0]  (value not drawn)
VB_PH1_1  0312-0-15-15-34-27-10-0  [Mill-Max_0312-0-15-15-34-27-10-0]  (value not drawn)
VB_PH1_2  0312-0-15-15-34-27-10-0  [Mill-Max_0312-0-15-15-34-27-10-0]  (value not drawn)
VB_PH2_1  0312-0-15-15-34-27-10-0  [Mill-Max_0312-0-15-15-34-27-10-0]  (value not drawn)
VB_PH2_2  0312-0-15-15-34-27-10-0  [Mill-Max_0312-0-15-15-34-27-10-0]  (value not drawn)

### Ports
5Vp (in), 12V_inrush (in), 12Vp (in), +BRDG_N, +BRDG_P, +BRDG_P (out), -BRDG_N, -BRDG_N (bidir), -BRDG_P, -BRDG_P (out), AC_CUR_SENSE, AC_L, AC_L1, AC_N, AC_N1, DRV_Relay (in), DRV_Relay (out), GaN_F1 (in), GaN_F2 (in), HS_TEMP1 (in), HS_TEMP2 (in), HS_ZVS1 (in), HS_ZVS2 (in), L_Wire (in), LS_TEMP1 (in), LS_TEMP2 (in), LS_ZVS1 (in), LS_ZVS2 (in), N_Wire (in), Neutral (bidir), PFCG_1H (in), PFCG_1L (in), PFCG_2H (in), PFCG_2L (in), PWM1A (in), PWM1B (in), RELAY_CTRL (in), Vbulk (in), Vbulk_out (in), Vcb (in), VDDB (bidir)

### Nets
AGND: C113.2 C114.2 C115.2 C117.2 C120.2 C122.2 C123.2 C127.2 C128.2 J1.10 J1.11 J1.12 J2.10 J2.11 J2.12 NT1.2 R121.1 TP103.1 U1.3(IN-) U1.4(GND1) U101.15(GND) U103.1(GND)
EARTH: C104.2 C105.1 C111.1 C112.2
PGND: C2.1 C3.1 C4.1 C5.1 C101.1 C102.1 C130.2 C131.2 D104.1(A) D104.3(A) D105.1(A) D105.3(A) J101.1 NT1.1 PGND_LF_1.1 PGND_LF_2.1 PGND_PH1_1.1 PGND_PH1_2.1 PGND_PH2_1.1 PGND_PH2_2.1
5Vp: C113.1 C114.1 C117.1 C120.1 J1.3 J2.3 U1.1(VCC1) U101.10(VCC) U103.4(VCCI) U103.7(VCCI) ; port 5Vp
12V_inrush: C1.1 U1.5(VCC2) ; port 12V_inrush
12Vp: C126.1 J1.1 J2.1 R117.2 U103.13(VDDA) ; port 12Vp
+BRDG_N: D103.2(A) J6.1 R105.1 ; port +BRDG_N
+BRDG_P: D106.2(A) J7.1 R114.1 ; port +BRDG_P
-BRDG_N: C116.2 C118.2 C119.1 J6.2 U103.8(VSSB) ; port -BRDG_N
-BRDG_P: C126.2 J7.2 U103.11(VSSA) ; port -BRDG_P
AC_CUR_SENSE: U101.12(VIOUT) ; port AC_CUR_SENSE
AC_L: C104.1 C108.2 L103.2 L106.4 ; port AC_L
AC_L1: C105.2 C109.2 D101.1(A) D101.3(A) D104.2(K) L1.2(F) L2.1(S) L103.3 ; port AC_L1
AC_N: C108.1 C111.2 L103.1 L106.3 ; port AC_N
AC_N1: C109.1 C112.1 L103.4 U101.5(IP-) U101.6(IP-) U101.7(IP-) U101.8(IP-) ; port AC_N1
DRV_Relay: R101.1 R104.1 R119.1 U1.7(OUTL) ; port DRV_Relay
GaN_F1: J1.8 ; port GaN_F1
GaN_F2: J2.8 ; port GaN_F2
HS_TEMP1: J1.7 ; port HS_TEMP1
HS_TEMP2: J2.7 ; port HS_TEMP2
HS_ZVS1: J1.5 ; port HS_ZVS1
HS_ZVS2: J2.5 ; port HS_ZVS2
L_Wire: L106.1 R107.2 R108.2 ; port L_Wire
LS_TEMP1: J1.4 ; port LS_TEMP1
LS_TEMP2: J2.4 ; port LS_TEMP2
LS_ZVS1: J1.2 ; port LS_ZVS1
LS_ZVS2: J2.2 ; port LS_ZVS2
N_Wire: L106.2 R112.1 R113.1 ; port N_Wire
Neutral: C106.1 C110.1 C124.1 D102.1(A) D102.3(A) D105.2(K) N_LF_1.1 N_LF_2.1 U101.1(IP+) U101.2(IP+) U101.3(IP+) U101.4(IP+) ; port Neutral
PFCG_1H: J1.9 ; port PFCG_1H
PFCG_1L: J1.6 ; port PFCG_1L
PFCG_2H: J2.9 ; port PFCG_2H
PFCG_2L: J2.6 ; port PFCG_2L
PWM1A: R120.2 ; port PWM1A
PWM1B: R118.2 ; port PWM1B
RELAY_CTRL: R122.2 ; port RELAY_CTRL
SW1: L1.1(S) L102.1 SW_PH1_1.1 SW_PH1_2.1
SW2: L2.2(F) L104.2 SW_PH2_1.1 SW_PH2_2.1
Vbulk: C2.2 C3.2 C4.2 C5.2 C130.1 C131.1 D101.2(K) D102.2(K) Q101.9(Drain) Q106.9(Drain) RT1.1 VB_LF_1.1 VB_LF_2.1 VB_PH1_1.1 VB_PH1_2.1 VB_PH2_1.1 VB_PH2_2.1 ; port Vbulk
Vbulk_out: C1.2 C101.2 C102.2 J101.3 Q101.2(Driver_Source) Q101.3-4-5-6-7-8(Source) Q106.2(Driver_Source) Q106.3-4-5-6-7-8(Source) R103.1 R106.1 RT1.2 TP101.1 U1.8(VEE2) ; port Vbulk_out
Vcb: C106.2 C110.2 C124.2 L102.2 L104.1 ; port Vcb
VDDB: C116.1 C118.1 C119.2 D107.1(K) U103.10(VDDB) ; port VDDB
NetC115_1: C115.1 U101.13(FILTER)
NetC122_1: C122.1 R118.1 U103.2(INA)
NetC123_1: C123.1 R120.1 U103.3(INB)
NetC127_1: C127.1 R121.2 U103.6(DT)
NetC128_1: C128.1 R122.1 U1.2(IN+)
NetD103_1: D103.1(K) R102.1
NetD106_1: D106.1(K) R111.1
NetD107_2: D107.2(A) R117.1
NetQ101_1: Q101.1(Gate) R103.2 R104.2
NetQ106_1: Q106.1(Gate) R101.2 R106.2
NetR102_2: R102.2 R105.2 U103.9(VOUTB)
NetR107_1: R107.1 R109.2
NetR108_1: R108.1 R110.2
NetR109_1: R109.1 R112.2
NetR110_1: R110.1 R113.2
NetR111_2: R111.2 R114.2 U103.12(VOUTA)
NetR119_2: R119.2 U1.6(OUTH)

Not connected (* = marked no-connect by the designer): J101 2; U101 9(NC)* 11(NC)* 14(NC)* 16(NC)*; U103 5(DISABLE)*

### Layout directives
net class HV_AC_N: AC_N, AC_N1, N_Wire, Neutral
net class HV_SW: SW1, SW2
net class HV_DC: (no net found under the mark), Vbulk, Vbulk_out
net class HV_AC_L: AC_L, AC_L1, L_Wire, Vcb
net class HV_AC_LF_SW: (no net found under the mark)

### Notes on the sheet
- Build on PMP40988 E3 Hardware
- Inrush Current Limit Circuit
- LF SR Board
- To Bulk Capacitors
- Input Card
- (near C104) EMI FILTER
- (near L1) Do not populate
- Short nodes together
- (near L102) Replace with 86H-22054C
- LMG3525 GaN
- Daughter Card #1
- (near L104) Replace with 86H-22054C
- 40mV/A
- (near L2) Do not populate
- (near U101) Alternate ACS724KMATR-65AB-T 30.75mV/A
- Daughter Card #2

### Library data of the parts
!PCB101 = PCB: Manufacturer: Any; PartNumber: PMP23475; SymbolCreator: a0412235
C1 = CMP-0007150-5: CAP, CERM, 1 uF, 35 V, +/- 10%, X5R, 0603; Manufacturer: Taiyo Yuden; TaMin_C: -55°C; Polarized: N; SizeAreaWB_mm2: 4.68; Value1: Unknown; U/M: EA; Value: 1uF; TaMax_C: 85°C; SizeZ_mm: 1; SizeX_mm: 1.6; SizeY_mm: 0.8; SizeArea_mm2: 1.28; Cap_F: 1µF; AEC Category: Q200
C2-C5 = CMP-0097403-1: Cap Ceramic 0.15uF 1000V X7R 10% SMD 2225 125°C Embossed Plastic T/R; Manufacturer: KEMET; AEC Qualified: No; Value: 150nF; SizeZ_mm: 2.7mm; TempCo: 15%
C101 C102 = GRM32DR72J473KW01L: CAP, CERM, 0.047 µF, 630 V, +/- 10%, X7R, 1210; Manufacturer: MuRata; Polarized: N; CompType: Capacitor; Value: 0.047uF; U/M: EA; Cap_F: 0.000000047; Tolerance_%: 10; Value1: Unknown; VDC_V: 630; TaMin_C: -55; TaMax_C: 125; Cap_Case: 1210; SizeArea_mm2: 8; SizeAreaWB_mm2: 14.7; SizeX_mm: 3.2; SizeY_mm: 2.5; SizeZ_mm: 2.2; AEC Category: Q200
C104 C105 C111 C112 = CMP-0009609-4: CAP, CERM, 1000 pF, X1 400 VAC/Y2 440 VAC, +/- 20%, E, TH; Manufacturer: MuRata; TaMin_C: -25°C; Polarized: N; SizeAreaWB_mm2: 66.5; Value1: Unknown; U/M: EA; Value: 1000pF; TaMax_C: 85°C; SizeZ_mm: 10; SizeX_mm: 7.5; SizeY_mm: 5; Cap_Case: 7x5x10mm; SizeArea_mm2: 37.5; CompType: Capacitor; Cap_F: 1.5nF; AEC Category: Q200; VDC_V: 400V; AC_Safety: X1Y2; VAC_Y: 440V
C106 C110 C124 = CMP-0092709-1: Cap Film 0.47uF 630V PP 10% Dipped 15mm 110°C Bulk; Manufacturer: KEMET; Voltage Ac Rating X: 310V; AEC Grade: Grade 2; Cap_F: 470nF; Value: 470nF; VAC_X: X2; AEC Qualified: Yes; SizeZ_mm: 18.6mm
C108 C109 = 890334026034: WCAP-FTXX Film Capacitor, THT, L26W15H25, 2.2uF, 310V; Manufacturer: Wurth Elektronik; Insulation Resistance: 10000Ohm x F; Capacitance Tolerance: +/-10%; Dissipation Factor@1kHz: 0.1%; Dissipation Factor@10kHz: 0.7%; Rate of Voltage Rise: 170V/us; Pitch: 22.5mm; Technical Reference: MX2P225225K275ASPB46000
C113 C120 = CMP-0860555-1: as C623 on sheet PCB_Project_PMP23475_Main_Board_E1_Control
C114 = GRM185R60J105KE26D: CAP, CERM, 1uF, 6.3V, +/-10%, X5R, 0603; Manufacturer: MuRata; Polarized: N; CompType: Capacitor; U/M: EA; Cap_F: 0.000001; Tolerance_%: 10; Value1: Unknown; VDC_V: 6.3; TaMin_C: -55; TaMax_C: 85
C115 = GRM155R60J102KA01D: CAP, CERM, 1000pF, 6.3V, +/-10%, X5R, 0402; Manufacturer: MuRata; Polarized: N; CompType: Capacitor; U/M: EA; Cap_F: 0.000000001; Tolerance_%: 10; Value1: Unknown; VDC_V: 6.3; TaMin_C: -55; TaMax_C: 85
C116 C118 C126 = CMP-0007827-2: CAP, CERM, 22 uF, 16 V, +/- 20%, X5R, 0805; Manufacturer: TDK; TaMin_C: -55°C; Polarized: N; SizeAreaWB_mm2: 6.75; Value1: Unknown; U/M: EA; Value: 22uF; TaMax_C: 85°C; SizeZ_mm: 1.45; SizeX_mm: 2; SizeY_mm: 1.25; Cap_Case: 0805; Value2: 16V; SizeArea_mm2: 2.5; CompType: Capacitor; Cap_F: 22µF; AEC Category: Q200
C117 = CMP-0081457-1: CAP, CERM, 1 µF, 10 V,+/- 20%, X5R, 0402; Manufacturer: Yageo America; TaMin_C: -55°C; Polarized: N; SizeAreaWB_mm2: 3; U/M: EA; Value: 1uF; TaMax_C: 85°C; SizeZ_mm: 0.6; SizeX_mm: 1; SizeY_mm: 0.5; Value2: 10V; CompType: Capacitor; AEC Category: Q200
C119 = C1608X7R1E105K080AB: CAP, CERM, 1uF, 25V, +/-10%, X7R, 0603; Manufacturer: TDK; Polarized: N; CompType: Capacitor; U/M: EA; Cap_F: 0.000001; Tolerance_%: 10; Value1: Unknown; VDC_V: 25; TaMin_C: -55; TaMax_C: 125
C122 C123 C128 = CMP-0006235-2: CAP, CERM, 1000 pF, 50 V, +/- 10%, X7R, 0402; Manufacturer: Kemet; TaMin_C: -55°C; Polarized: N; SizeAreaWB_mm2: 3; Value1: Unknown; U/M: EA; Value: 1000pF; TaMax_C: 125°C; SizeZ_mm: 0.6; SizeX_mm: 1; SizeY_mm: 0.5; Value2: 50V; CompType: Capacitor; Cap_F: 1nF; AEC Category: Q200
C127 = CMP-0860557-1: CAP, CERM, 4700 pF, 25 V,+/- 10%, X7R, 0402; Manufacturer: Yageo; Polarized: N; SizeY_mm: 0.5; VDC_V: 25V; Green_Lifecycle: Active; Value: 4700pF; TaMin_C: -55°C; TaMax_C: 125°C; SizeZ_mm: 0.6; U/M: EA; SizeAreaWB_mm2: 3; Cap_F: 4.7nF; SizeX_mm: 1; AEC Category: Q200; CompType: Capacitor; Green_REACh: Passed
C130 C131 = CMP-0009326-2: CAP, CERM, 0.1 uF, 1000 V, +/- 10%, X7R, 1812; Manufacturer: Kemet; Polarized: N; CompType: Capacitor; Value: 0.1uF; U/M: EA; Cap_F: 100nF; Value1: Unknown; Value2: 1000V; TaMin_C: -55°C; TaMax_C: 125°C; Cap_Case: 1812; AEC Category: Q200; SizeArea_mm2: 14.4; SizeAreaWB_mm2: 23.1; SizeX_mm: 4.5; SizeY_mm: 3.2; SizeZ_mm: 2.54
D101 D102 D104 D105 = CMP-0077041-3: Diode, Ultrafast, 600 V, 15 A, DPAK; Manufacturer: VISHAY; SizeX_mm: 9.91; Io_A: 15A; TJmax_C: 175°C; Green_Lifecycle: Not Set; Green_REACh: Incomplete; SizeZ_mm: 2.29; SizeY_mm: 6.54; SizeArea_mm2: 64.8114; SizeAreaWB_mm2: 101.7114; Value2: 1.15V; RJC_CperW: 2.5; Value: 600V; AEC Category: Q101
D103 D106 = CMP-0028458-2: Diode, Schottky, 30 V, 0.2 A, SOD-323; Manufacturer: Diodes Inc.; SizeArea_mm2: 3.645; Green_Lifecycle: Active; Io_A: 2dA; TJmax_C: 125°C; Value2: 0.7V; Vf_V: 7dV; Green_REACh: Passed; Value1: 0.2A; Vr_V: 30V; AEC Category: Q101; SizeAreaWB_mm2: 8.695; SizeY_mm: 1.35; Value: 30V; SizeX_mm: 2.7; SizeZ_mm: 1
D107 = MURA160T3G: Diode, Ultrafast, 600V, 1A, SMA; Manufacturer: ON Semiconductor; U/M: EA; Vf_V: 1.05; Value2: 1.05V; Io_A: 1; Vr_V: 600; TJmax_C: 175
J1 J2 = CMP-0094055-1: 12 Position Receptacle Connector 0.050" (1.27mm) Through Hole Gold; Manufacturer: Harwin; AEC Qualified: No; Is Female: yes; ContactFinish: Gold,Nickel; SizeZ_mm: 4.55mm; Current_A: 1A; Conn Gender: Female; Conn Orientation: Vertical; Row_Count: 2
J6 J7 = CMP-0097274-1: 2 Position Receptacle Connector 0.050" (1.27mm) Through Hole Gold; Manufacturer: Harwin; ContactFinish: Gold,Nickel; Current_A: 1A; Is Female: yes; AEC Qualified: No; Row_Count: 1; Conn Gender: Female; Conn Orientation: Vertical; SizeZ_mm: 4.55mm
J101 = 282856-3: Receptacle, 3x1, 5mm, R/A, TH; Manufacturer: TE Connectivity; SymbolCreator: a0412235; CompType: Terminal Block; Pitch_mm: 5; Gender: Female; Row_Count: 1; ContactFinish: Tin; Current_A: 24; Voltage_V: 300; Cert_UL: Y
L1 L2 = CMP-0096870-1: Inductor, Buck/Boost, EDY35, TH; Manufacturer: Pulse; Tolerance_%: 10%; Isat: 21.5A; DCR_ohm: 24m; SizeZ_mm: 30mm; AEC Qualified: No; Value: 140uH; Ind_H: 140µH; Test Frequency: 100kHz
L102 L104 = CMP-0097059-1: Inductor 16.2uH 12mOhm 30x14.2x33.3 TH; Manufacturer: Delta Electronics; AEC Qualified: No; Test Frequency: 200kHz; Standoff Height: 0.2mm; SizeZ_mm: 33.3mm; DCR_ohm: 12m; Ind_H: 16.2µH
L103 = CMP-0097286-1: Common Mode Choke 2.8mH 3.8mΩ; Manufacturer: Sunlord; Material: Nanocrystalline; SizeZ_mm: 30mm; Test Frequency: 10kHz; AEC Qualified: No; DCR_ohm: 3.8m; Tolerance_%: 25%
L106 = CMP-0097287-1: COMMON MODE CHOKE 1mH @ 10kHz 2.4mohm 1000VAC; Manufacturer: Yaxin Electronics; DCR_ohm: 2.4m; Ind_H: 1.8mH; AEC Qualified: No; SizeZ_mm: 24.5mm; Material: JC-2008-R01
N_LF_1 N_LF_2 PGND_LF_1 PGND_LF_2 PGND_PH1_1 PGND_PH1_2 PGND_PH2_1 PGND_PH2_2 SW_PH1_1 SW_PH1_2 SW_PH2_1 SW_PH2_2 VB_LF_1 VB_LF_2 VB_PH1_1 VB_PH1_2 VB_PH2_1 VB_PH2_2 = CMP-0055026-1: Pin Receptacle, .032-.046" .075" Dia, Gold, TH; Manufacturer: Mill-Max; CNHeader: FALSE; Green_Lifecycle: Active; Gender: Female; Green_REACh: Passed
NT1 = CMP-0078142-6: Single point connection between nets.
Q101 Q106 = CMP-0086487-1: MOSFET N-CH 650V 23A HSOF-8; Manufacturer: Infineon; QgTyp_nC: 150nC @ 10V; Rdson45_ohm: 0.022; Vgs_V: 20V; AEC Qualified: No; ChMode: False; SizeZ_mm: 2.4mm
R101 R104 = CMP-0022900-4: RES, 1.00, 1%, 0.1 W, 0603; Manufacturer: Yageo; Power_W: 100mW; TempCo: 200 ppm/C; Value_Code: 1R00; Value: 1.00; EIA_Code: E96; Res_ohm: 1; SizeX_mm: 1.6; SizeY_mm: 0.8; Value2: 0.1W; SizeArea_mm2: 1.28; AEC Qualified: N; VDC_V: 75V; AEC Category: Q200; SizeAreaWB_mm2: 4.68
R102 R111 = CMP-0022751-4: RES, 10.0, 1%, 0.1 W, 0603; Manufacturer: Yageo; Power_W: 100mW; TempCo: 100 ppm/C; Value_Code: 10R0; Value: 10.0; EIA_Code: E96; Res_ohm: 10; SizeX_mm: 1.6; SizeY_mm: 0.8; SizeZ_mm: 1; Value2: 0.1W; SizeArea_mm2: 1.28; AEC Qualified: N; VDC_V: 75V; AEC Category: Q200; SizeAreaWB_mm2: 4.68
R103 R106 = CMP-0022746-5: RES, 10.0 k, 1%, 0.1 W, 0603; Manufacturer: Yageo; Power_W: 100mW; TempCo: 100 ppm/C; Value_Code: 10k0; Value: 10.0k; EIA_Code: E96; Res_ohm: 10k; SizeX_mm: 1.6; SizeY_mm: 0.8; SizeZ_mm: 1; Value2: 0.1W; SizeArea_mm2: 1.28; AEC Qualified: N; VDC_V: 75V; AEC Category: Q200; SizeAreaWB_mm2: 4.68
R105 R114 = CMP-0022895-5: RES, 1.00 k, 1%, 0.1 W, 0603; Manufacturer: Yageo; Power_W: 100mW; TempCo: 100 ppm/C; Value_Code: 1k00; Value: 1.00k; EIA_Code: E96; Res_ohm: 1k; SizeX_mm: 1.6; SizeY_mm: 0.8; SizeZ_mm: 1; Value2: 0.1W; SizeArea_mm2: 1.28; AEC Qualified: N; VDC_V: 75V; AEC Category: Q200; SizeAreaWB_mm2: 4.68
R107-R110 R112 R113 = CMP-0017836-2: RES, 100 k, 1%, 0.25 W, 1206; Manufacturer: Yageo America; Power_W: 250mW; TempCo: 100 ppm/C; U/M: EA; Value: 100k; EIA_Code: E96; SizeX_mm: 3.2; SizeY_mm: 1.6; SizeZ_mm: 1.35; Value2: 0.25W; SizeArea_mm2: 5.12; VDC_V: 200V; AEC Category: Q200
R117 = CMP-0022908-4: RES, 20.0, 1%, 0.1 W, 0603; Manufacturer: Yageo; Power_W: 100mW; TempCo: 100 ppm/C; Value_Code: 20R0; Value: 20.0; EIA_Code: E96; Res_ohm: 20; SizeX_mm: 1.6; SizeY_mm: 0.8; SizeZ_mm: 1; Value2: 0.1W; SizeArea_mm2: 1.28; AEC Qualified: N; VDC_V: 75V; AEC Category: Q200; SizeAreaWB_mm2: 4.68
R118 R120 R122 = CRCW04021K00JNED: RES, 1.0k ohm, 5%, 0.063W, 0402; Manufacturer: Vishay-Dale; CompType: Resistor; Res_ohm: 1000; Value_Code: 1k00; Tolerance_%: 5; Power_W: 0.063; VDC_V: 50; TempCo: 200 ppm/C; EIA_Code: E24; U/M: EA
R119 = CMP-0023206-5: RES, 5.11, 1%, 0.1 W, 0603; Manufacturer: Yageo; Power_W: 100mW; TempCo: 200 ppm/C; Value_Code: 5R11; Value: 5.11; EIA_Code: E96; SizeX_mm: 1.6; SizeY_mm: 0.8; SizeZ_mm: 1; Value2: 0.1W; SizeArea_mm2: 1.28; AEC Qualified: N; VDC_V: 75V; AEC Category: Q200; SizeAreaWB_mm2: 4.68
R121 = CMP-0026727-1: RES, 1.00 M, 1%, 0.063 W, 0402; Manufacturer: Yageo America; Power_W: 63mW; TempCo: 100 ppm/C; Value_Code: 1M00; U/M: EA; Value: 1.00Meg; EIA_Code: E96; Res_ohm: 1M; SizeX_mm: 1; SizeY_mm: 0.5; SizeZ_mm: 0.6; Value2: 0.063W; AEC Category: Q200
RT1 = CMP-0002554-2: Thermistor NTC, 4.70 ohm, 20%, 15x7mm; Manufacturer: TDK; TaMax_C: 170°C; SizeX_mm: 15; SizeY_mm: 7.5; TaMin_C: -55°C; Power_W: 3.1W; SizeZ_mm: 47; SizeArea_mm2: 112.5; SizeAreaWB_mm2: 161.5; U/M: EA
TP101 = 5000: Test Point, Miniature, Red, TH; Manufacturer: Keystone; CompType: Test Point Loop; U/M: EA
TP103 = 5001: Test Point, Miniature, Black, TH; Manufacturer: Keystone; CompType: Test Point Loop; U/M: EA
U1 = CMP-0077706-1: 3-kVRMS Single-Channel Isolated Gate Drivers, D0008B (SOIC-8); Alternate Manufacturer: Texas Instruments; SizeAreaWB_mm2: 55.2; SizeZ_mm: 1.75; SizeX_mm: 6.0; SizeY_mm: 4.9; SizeArea_mm2: 29.4; CompType: IC; AEC Qualified: N; AEC Category: Q200
U101 = CMP-0077522-2: High Accuracy, Hall-Effect Based Current Sensor, SOIC-16; Manufacturer: Allegro Microsystems Inc
U103 = CMP-0013548-2: 4A/6A Isolated Dual-Channel Gate Driver, NPL0013A (VLGA-13); Manufacturer: Texas Instruments; SizeX_mm: 5; CompType: IC; SizeZ_mm: 1; SizeArea_mm2: 25; SizeAreaWB_mm2: 49; U/M: EA

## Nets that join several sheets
AGND: PCB_Project_PMP23475_Main_Board_E1_Control (38 pins), PCB_Project_PMP23475_Main_Board_E1_Power (22 pins)
5Vp: PCB_Project_PMP23475_Main_Board_E1_Control (8 pins), PCB_Project_PMP23475_Main_Board_E1_Power (10 pins)
12V_inrush: PCB_Project_PMP23475_Main_Board_E1_Control (J9.3), PCB_Project_PMP23475_Main_Board_E1_Power (C1.1 U1.5)
12Vp: PCB_Project_PMP23475_Main_Board_E1_Control (7 pins), PCB_Project_PMP23475_Main_Board_E1_Power (5 pins)
-BRDG_N: PCB_Project_PMP23475_Main_Board_E1_Control (J9.4), PCB_Project_PMP23475_Main_Board_E1_Power (5 pins)
AC_CUR_SENSE: PCB_Project_PMP23475_Main_Board_E1_Control (R609.1), PCB_Project_PMP23475_Main_Board_E1_Power (U101.12)
AC_L: PCB_Project_PMP23475_Main_Board_E1_Control (R603.2), PCB_Project_PMP23475_Main_Board_E1_Power (C104.1 C108.2 L103.2 L106.4)
AC_N: PCB_Project_PMP23475_Main_Board_E1_Control (R604.2), PCB_Project_PMP23475_Main_Board_E1_Power (C108.1 C111.2 L103.1 L106.3)
GaN_F1: PCB_Project_PMP23475_Main_Board_E1_Control (J602.4), PCB_Project_PMP23475_Main_Board_E1_Power (J1.8)
GaN_F2: PCB_Project_PMP23475_Main_Board_E1_Control (J602.6), PCB_Project_PMP23475_Main_Board_E1_Power (J2.8)
HS_TEMP1: PCB_Project_PMP23475_Main_Board_E1_Control (R620.1), PCB_Project_PMP23475_Main_Board_E1_Power (J1.7)
HS_TEMP2: PCB_Project_PMP23475_Main_Board_E1_Control (R626.1), PCB_Project_PMP23475_Main_Board_E1_Power (J2.7)
HS_ZVS1: PCB_Project_PMP23475_Main_Board_E1_Control (C609.1 J602.8), PCB_Project_PMP23475_Main_Board_E1_Power (J1.5)
HS_ZVS2: PCB_Project_PMP23475_Main_Board_E1_Control (C614.1 J602.12), PCB_Project_PMP23475_Main_Board_E1_Power (J2.5)
LS_TEMP1: PCB_Project_PMP23475_Main_Board_E1_Control (R623.1), PCB_Project_PMP23475_Main_Board_E1_Power (J1.4)
LS_TEMP2: PCB_Project_PMP23475_Main_Board_E1_Control (R637.1), PCB_Project_PMP23475_Main_Board_E1_Power (J2.4)
LS_ZVS1: PCB_Project_PMP23475_Main_Board_E1_Control (C612.1 J602.10), PCB_Project_PMP23475_Main_Board_E1_Power (J1.2)
LS_ZVS2: PCB_Project_PMP23475_Main_Board_E1_Control (C616.1 J602.14), PCB_Project_PMP23475_Main_Board_E1_Power (J2.2)
PFCG_1H: PCB_Project_PMP23475_Main_Board_E1_Control (J602.3), PCB_Project_PMP23475_Main_Board_E1_Power (J1.9)
PFCG_1L: PCB_Project_PMP23475_Main_Board_E1_Control (J602.5), PCB_Project_PMP23475_Main_Board_E1_Power (J1.6)
PFCG_2H: PCB_Project_PMP23475_Main_Board_E1_Control (J601.20), PCB_Project_PMP23475_Main_Board_E1_Power (J2.9)
PFCG_2L: PCB_Project_PMP23475_Main_Board_E1_Control (J602.2), PCB_Project_PMP23475_Main_Board_E1_Power (J2.6)
PWM1A: PCB_Project_PMP23475_Main_Board_E1_Control (J601.19), PCB_Project_PMP23475_Main_Board_E1_Power (R120.2)
PWM1B: PCB_Project_PMP23475_Main_Board_E1_Control (J602.1), PCB_Project_PMP23475_Main_Board_E1_Power (R118.2)
RELAY_CTRL: PCB_Project_PMP23475_Main_Board_E1_Control (J602.7), PCB_Project_PMP23475_Main_Board_E1_Power (R122.2)
Vbulk_out: PCB_Project_PMP23475_Main_Board_E1_Control (J9.1 R602.2), PCB_Project_PMP23475_Main_Board_E1_Power (13 pins)
Vcb: PCB_Project_PMP23475_Main_Board_E1_Control (R621.2), PCB_Project_PMP23475_Main_Board_E1_Power (5 pins)
VDDB: PCB_Project_PMP23475_Main_Board_E1_Control (R1.2), PCB_Project_PMP23475_Main_Board_E1_Power (5 pins)

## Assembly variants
001: not fitted R615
